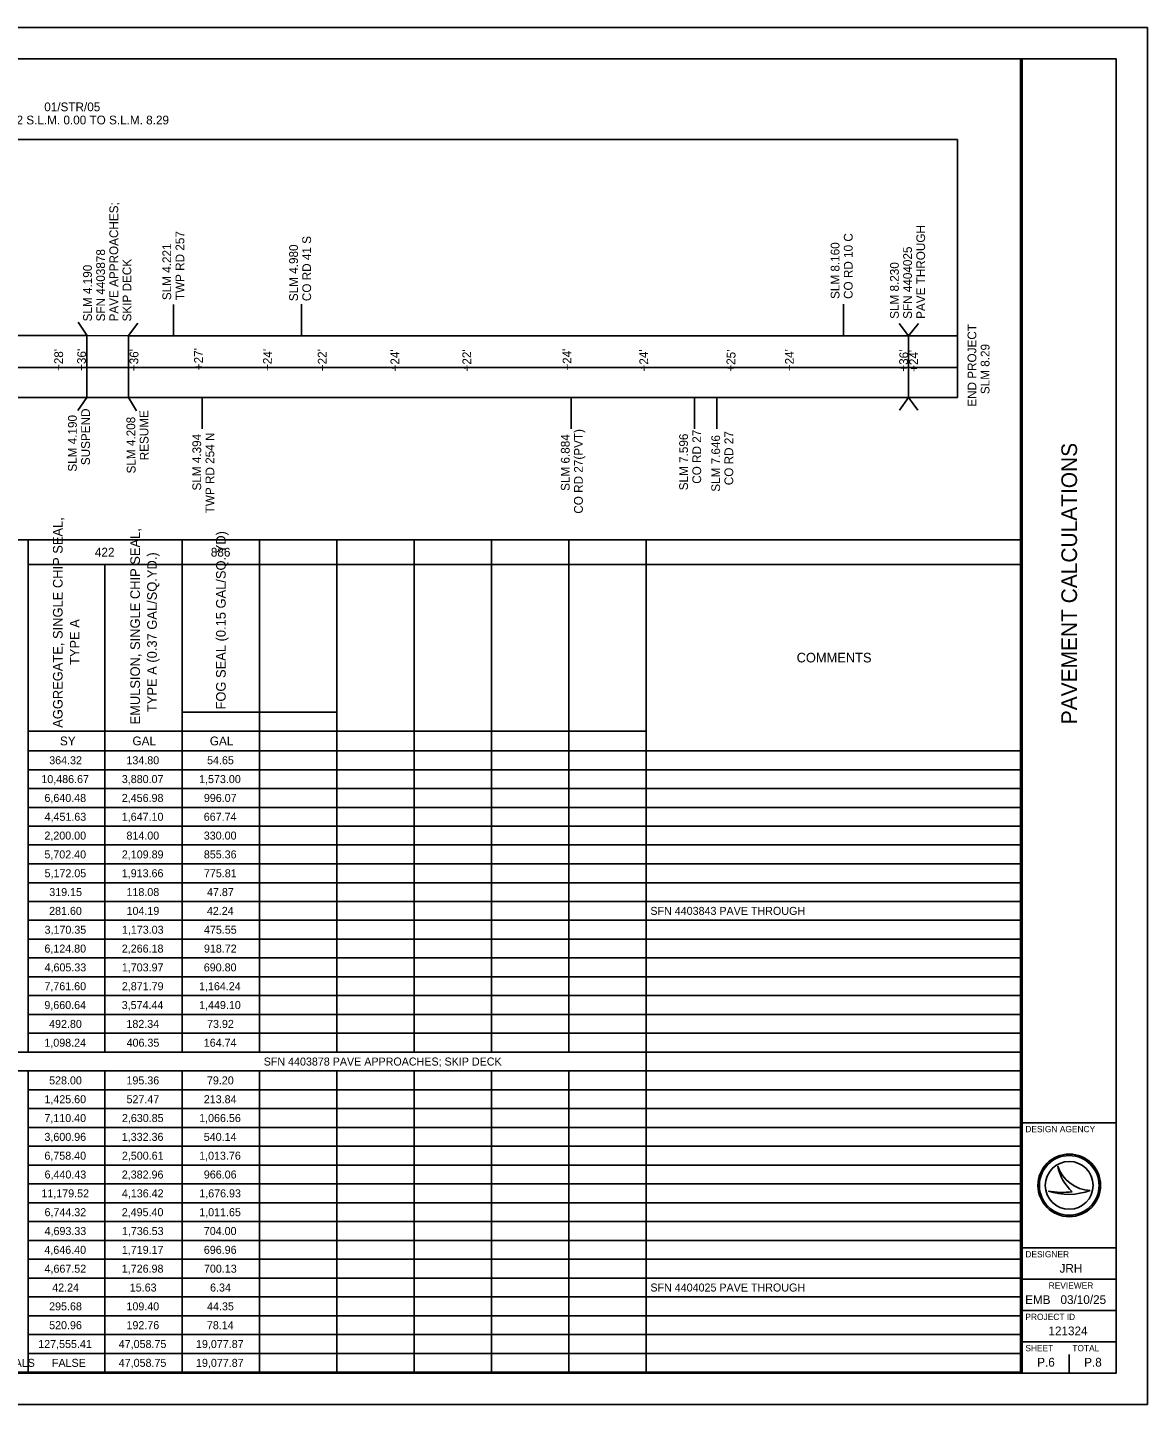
# Model space of a CAD drawing. Extents: x 0 to 680, y 0 to 440.
# Drawn here: x 322.2 to 680, y 0 to 440 of the extents above; entities that cross this region are included whole.
import ezdxf

# ---------------------------------------------------------------- set-up
doc = ezdxf.new("R2010")
doc.units = 0
for name, color, linetype in [('Default', 7, 'Continuous'), ('SH_Border', 7, 'Continuous'), ('SH_Cut_Line', 7, 'Continuous'), ('SH_Data', 7, 'Continuous'), ('SH_Text', 7, 'Continuous')]:
    doc.layers.add(name, color=color, linetype=linetype)

msp = doc.modelspace()

# ---------------------------------------------------------------- linework, layer by layer
at = {"layer": 'Default'}
for p, q in [((30, 430), (639.48, 430)), ((639.48, 430), (639.48, 10.29)), ((50.79, 404.2), (619.28, 404.2)), ((619.28, 381.75), (619.28, 404.2)), ((619.28, 404.2), (619.28, 341.75)), ((368.88, 341.52), (368.88, 351.52)), ((409.72, 341.56), (409.72, 351.56)), ((582.86, 341.61), (582.86, 351.61)), ((603.7, 341.5), (600.65, 345.46)), ((603.7, 341.5), (606.81, 345.41)), ((603.7, 321.77), (603.7, 341.49)), ((619.28, 341.75), (619.28, 321.78)), ((50.99, 331.41), (619.48, 331.36)), ((378.01, 321.75), (378.01, 311.75)), ((495.89, 321.8), (495.89, 311.8)), ((535.26, 321.78), (535.26, 311.78)), ((542.43, 321.77), (542.43, 311.77)), ((603.68, 321.78), (600.78, 317.71)), ((603.71, 321.78), (606.64, 317.73)), ((279.5, 276.26), (322.44, 276.26)), ((322, 276.26), (639.48, 276.26)), ((322.44, 276.26), (322.44, 112.59)), ((371.64, 276.26), (371.64, 112.59)), ((396.34, 276.26), (396.34, 112.59)), ((421.05, 276.26), (421.05, 112.59)), ((445.76, 276.26), (445.76, 112.59)), ((470.47, 276.26), (470.47, 112.59)), ((495.18, 276.26), (495.18, 112.59)), ((519.89, 276.26), (519.89, 10.29)), ((322.44, 268.44), (639.48, 268.44)), ((346.93, 268.44), (346.93, 112.59)), ((371.64, 221.2), (421.05, 221.2)), ((322.44, 215.18), (519.89, 215.18)), ((322.44, 208.86), (639.48, 208.86)), ((322.44, 202.85), (639.48, 202.85)), ((322.44, 196.83), (639.48, 196.83)), ((322.44, 190.81), (639.48, 190.81)), ((322.44, 184.79), (639.48, 184.79)), ((322.44, 178.78), (639.48, 178.78)), ((322.44, 172.76), (639.48, 172.76)), ((322.44, 166.74), (639.48, 166.74)), ((322.44, 160.73), (639.48, 160.73)), ((322.44, 154.71), (639.48, 154.71)), ((322.44, 148.69), (639.48, 148.69)), ((322.44, 142.67), (639.48, 142.67)), ((322.44, 136.66), (639.48, 136.66)), ((322.44, 130.64), (639.48, 130.64)), ((322.44, 124.62), (639.48, 124.62)), ((322.44, 118.6), (639.48, 118.6)), ((30, 112.59), (322.44, 112.59)), ((322, 112.59), (639.48, 112.59)), ((30, 106.57), (322.44, 106.57)), ((322, 106.57), (639.48, 106.57)), ((322.44, 106.57), (322.44, 10.29)), ((346.93, 106.57), (346.93, 10.29)), ((371.64, 106.57), (371.64, 10.29)), ((396.34, 106.57), (396.34, 10.29)), ((421.05, 106.57), (421.05, 10.29)), ((445.76, 106.57), (445.76, 10.29)), ((470.47, 106.57), (470.47, 10.29)), ((495.18, 106.57), (495.18, 10.29)), ((322.44, 100.55), (639.48, 100.55)), ((322.44, 94.53), (639.48, 94.53)), ((322.44, 88.52), (639.48, 88.52)), ((322.44, 82.5), (639.48, 82.5)), ((322.44, 76.48), (639.48, 76.48)), ((322.44, 70.47), (639.48, 70.47)), ((322.44, 64.45), (639.48, 64.45)), ((322.44, 58.43), (639.48, 58.43)), ((322.44, 52.41), (639.48, 52.41)), ((322.44, 46.4), (639.48, 46.4)), ((322.44, 40.38), (639.48, 40.38)), ((322.44, 34.36), (639.48, 34.36)), ((322.44, 28.34), (639.48, 28.34)), ((322.44, 22.33), (639.48, 22.33)), ((322.44, 16.31), (639.48, 16.31)), ((30, 10.29), (322.44, 10.29)), ((322, 10.29), (639.48, 10.29))]:
    msp.add_line(p, q, dxfattribs=at)
at = {"layer": 'SH_Border'}
for p, q in [((640, 10), (640, 430)), ((640, 90), (670, 90)), ((640, 50), (670, 50)), ((640, 40), (670, 40)), ((640, 30), (670, 30)), ((640, 20), (670, 20))]:
    msp.add_line(p, q, dxfattribs=at)
msp.add_lwpolyline([(30, 430), (670, 430), (670, 10), (30, 10)], close=True, dxfattribs=at)
at = {"layer": 'SH_Cut_Line'}
msp.add_lwpolyline([(0, 0), (680, 0), (680, 440), (0, 440)], close=True, dxfattribs=at)
at = {"layer": 'SH_Data'}
for p, q in [((651.35, 76.19), (651.35, 76.19)), ((648.34, 68.19), (648.34, 68.19)), ((655, 70), (655, 70)), ((661.75, 68.37), (661.75, 68.37)), ((647.5, 13.5), (647.5, 13.5)), ((655, 10), (655, 16))]:
    msp.add_line(p, q, dxfattribs=at)
for radius in [10, 9.54, 9.54, 7.64]:
    msp.add_circle((655, 70), radius, dxfattribs=at)
for centre, radius, start, end in [((662.32, 79.95), 11.6, 198.9257, 198.9319), ((666.93, 79.4), 15.91, 191.6379, 191.6421), ((662.32, 79.95), 11.6, 198.9319, 267.1657), ((666.93, 79.4), 15.91, 191.6421, 226.0947), ((654.79, 87.4), 20.26, 251.4576, 290.0832), ((652.96, 93.09), 25.32, 259.4964, 259.4995), ((654.79, 87.4), 20.26, 251.4527, 251.4576), ((652.96, 93.09), 25.32, 259.4995, 276.6672)]:
    msp.add_arc(centre, radius, start, end, dxfattribs=at)
at = {"layer": 'SH_Text'}
for p, q in [((341.13, 341.72), (338.36, 345.88)), ((354.43, 341.58), (357.47, 345.55)), ((50.76, 341.74), (619.36, 341.5)), ((341.18, 341.72), (341.18, 321.76)), ((354.47, 341.63), (354.47, 321.75)), ((50.99, 331.41), (619.48, 331.36)), ((50.79, 321.78), (619.28, 321.78)), ((341.15, 321.73), (338.33, 317.6)), ((354.47, 321.77), (357.02, 317.47))]:
    msp.add_line(p, q, dxfattribs=at)
for points in [[(341.18, 341.62), (341.18, 331.38), (199.88, 331.39), (341.18, 331.38), (341.18, 321.78), (50.79, 321.78), (50.79, 341.74)], [(619.28, 341.5), (619.28, 331.36), (354.48, 331.28), (354.48, 341.51)], [(619.28, 331.36), (619.28, 321.78), (341.18, 321.78), (341.18, 331.38)]]:
    msp.add_lwpolyline(points, close=True, dxfattribs=at)

# ---------------------------------------------------------------- texts
at = {"layer": 'Default'}
for s, height, p in [('01/STR/05', 2.8, (327.56, 413.25)), ('LAW-522 S.L.M. 0.00 TO S.L.M. 8.29', 2.8, (305.18, 409.05)), ('422', 2.813, (343.73, 270.94)), ('886', 2.813, (380.76, 270.94)), ('COMMENTS', 3.069, (567.92, 237.12)), ('SY', 2.813, (332.56, 210.62)), ('GAL', 2.813, (355.74, 210.62)), ('GAL', 2.813, (380.45, 210.62)), ('364.32', 2.557, (329.15, 204.58)), ('134.80', 2.557, (353.82, 204.58)), ('54.65', 2.557, (379.58, 204.58)), ('10,486.67', 2.557, (326.63, 198.56)), ('3,880.07', 2.557, (352.34, 198.56)), ('1,573.00', 2.557, (377.03, 198.56)), ('6,640.48', 2.557, (327.62, 192.54)), ('2,456.98', 2.557, (352.33, 192.54)), ('996.07', 2.557, (378.55, 192.54)), ('4,451.63', 2.557, (327.66, 186.52)), ('1,647.10', 2.557, (352.32, 186.52)), ('667.74', 2.557, (378.52, 186.52)), ('2,200.00', 2.557, (327.61, 180.51)), ('814.00', 2.557, (353.82, 180.51)), ('330.00', 2.557, (378.53, 180.51)), ('5,702.40', 2.557, (327.61, 174.49)), ('2,109.89', 2.557, (352.35, 174.49)), ('855.36', 2.557, (378.54, 174.49)), ('5,172.05', 2.557, (327.66, 168.47)), ('1,913.66', 2.557, (352.33, 168.47)), ('775.81', 2.557, (378.57, 168.47)), ('319.15', 2.557, (329.16, 162.46)), ('118.08', 2.557, (353.83, 162.46)), ('47.87', 2.557, (379.56, 162.46)), ('281.60', 2.557, (329.11, 156.44)), ('104.19', 2.557, (353.85, 156.44)), ('42.24', 2.557, (379.52, 156.44)), ('SFN 4403843 PAVE THROUGH', 2.5574, (521.2, 156.44)), ('3,170.35', 2.557, (327.66, 150.42)), ('1,173.03', 2.557, (352.37, 150.42)), ('475.55', 2.557, (378.58, 150.42)), ('6,124.80', 2.557, (327.61, 144.4)), ('2,266.18', 2.557, (352.33, 144.4)), ('918.72', 2.557, (378.57, 144.4)), ('4,605.33', 2.557, (327.66, 138.39)), ('1,703.97', 2.557, (352.34, 138.39)), ('690.80', 2.557, (378.53, 138.39)), ('7,761.60', 2.557, (327.61, 132.37)), ('2,871.79', 2.557, (352.35, 132.37)), ('1,164.24', 2.557, (377.01, 132.37)), ('9,660.64', 2.557, (327.6, 126.35)), ('3,574.44', 2.557, (352.31, 126.35)), ('1,449.10', 2.557, (377.03, 126.35)), ('492.80', 2.557, (329.11, 120.33)), ('182.34', 2.557, (353.81, 120.33)), ('73.92', 2.557, (379.58, 120.33)), ('1,098.24', 2.557, (327.6, 114.32)), ('406.35', 2.557, (353.87, 114.32)), ('164.74', 2.557, (378.52, 114.32)), ('SFN 4403878 PAVE APPROACHES; SKIP DECK', 2.5574, (397.66, 108.3)), ('528.00', 2.557, (329.11, 102.28)), ('195.36', 2.557, (353.83, 102.28)), ('79.20', 2.557, (379.53, 102.28)), ('1,425.60', 2.557, (327.61, 96.26)), ('527.47', 2.557, (353.84, 96.26)), ('213.84', 2.557, (378.52, 96.26)), ('7,110.40', 2.557, (327.61, 90.25)), ('2,630.85', 2.557, (352.37, 90.25)), ('1,066.56', 2.557, (377.04, 90.25)), ('3,600.96', 2.557, (327.62, 84.23)), ('1,332.36', 2.557, (352.33, 84.23)), ('540.14', 2.557, (378.52, 84.23)), ('6,758.40', 2.557, (327.61, 78.21)), ('2,500.61', 2.557, (352.36, 78.21)), ('1,013.76', 2.557, (377.04, 78.21)), ('6,440.43', 2.557, (327.66, 72.2)), ('2,382.96', 2.557, (352.33, 72.2)), ('966.06', 2.557, (378.54, 72.2)), ('11,179.52', 2.557, (326.65, 66.18)), ('4,136.42', 2.557, (352.36, 66.18)), ('1,676.93', 2.557, (377.08, 66.18)), ('6,744.32', 2.557, (327.65, 60.16)), ('2,495.40', 2.557, (352.32, 60.16)), ('1,011.65', 2.557, (377.07, 60.16)), ('4,693.33', 2.557, (327.66, 54.14)), ('1,736.53', 2.557, (352.37, 54.14)), ('704.00', 2.557, (378.53, 54.14)), ('4,646.40', 2.557, (327.61, 48.13)), ('1,719.17', 2.557, (352.34, 48.13)), ('696.96', 2.557, (378.54, 48.13)), ('4,667.52', 2.557, (327.65, 42.11)), ('1,726.98', 2.557, (352.33, 42.11)), ('700.13', 2.557, (378.58, 42.11)), ('42.24', 2.557, (330.11, 36.09)), ('15.63', 2.557, (354.88, 36.09)), ('6.34', 2.557, (380.53, 36.09)), ('SFN 4404025 PAVE THROUGH', 2.5574, (521.2, 36.09)), ('295.68', 2.557, (329.12, 30.07)), ('109.40', 2.557, (353.82, 30.07)), ('44.35', 2.557, (379.58, 30.07)), ('520.96', 2.557, (329.12, 24.06)), ('192.76', 2.557, (353.83, 24.06)), ('78.14', 2.557, (379.52, 24.06)), ('127,555.41', 2.557, (325.64, 18.04)), ('47,058.75', 2.557, (351.36, 18.04)), ('19,077.87', 2.557, (376.04, 18.04)), ('THIS SHEET TOTALS', 2.5574, (290.15, 12.02)), ('FALSE', 2.557, (330.01, 12.02)), ('47,058.75', 2.557, (351.36, 12.02)), ('19,077.87', 2.557, (376.04, 12.02))]:
    msp.add_text(s, height=height, dxfattribs=at).set_placement(p)
for s, height, rotation, p in [('PAVE APPROACHES;', 2.8, 90, (351.17, 346.09)), ('TWP RD 257', 2.8, 90, (372.3, 352.89)), ('CO RD 10 C', 2.8, 90, (585.81, 353.27)), ('PAVE THROUGH', 2.8, 90, (608.96, 346.91)), ('SLM 4.221', 2.8, 90, (368.1, 352.89)), ('SLM 4.980', 2.8, 90, (408.6, 352.57)), ('CO RD 41 S', 2.8, 90, (412.8, 352.57)), ('SLM 8.160', 2.8, 90, (581.61, 353.27)), ('SFN 4404025', 2.8, 90, (604.76, 346.91)), ('SFN 4403878', 2.8, 90, (346.97, 346.09)), ('SKIP DECK', 2.8, 90, (355.37, 346.09)), ('SLM 4.190', 2.8, 90, (342.77, 346.09)), ('SLM 8.230', 2.8, 90, (600.56, 346.91)), ('END PROJECT', 2.8, 90, (625.33, 318.82)), ("+28'", 2.8, 89.3296, (333.51, 330.21)), ("+36'", 2.8, 88.6689, (340.79, 330.23)), ("+36'", 2.8, 88.6689, (357.53, 330.17)), ("+27'", 2.8, 90.7703, (378.28, 330.52)), ("+24'", 2.8, 88.5554, (400.17, 330.19)), ("+22'", 2.8, 90.7703, (417.81, 330.19)), ("+24'", 2.8, 90.8026, (441.03, 330.11)), ("+22'", 2.8, 90.7703, (464, 330.11)), ("+24'", 2.8, 91.2033, (496.04, 330.37)), ("+24'", 2.8, 91.2033, (520.55, 330.13)), ("+25'", 2.8, 87.8363, (548.2, 329.97)), ("+24'", 2.8, 90.7703, (567.06, 330.18)), ("+36'", 2.8, 88.6689, (603.42, 329.98)), ("+24'", 2.8, 91.2033, (606.78, 329.98)), ('SLM 8.29', 2.8, 90, (629.53, 322.86)), ('       SLM 4.394', 2.8, 90, (377.68, 284.77)), ('TWP RD 254 N', 2.8, 90, (381.88, 284.77)), ('       SLM 6.884', 2.8, 90, (495.41, 284.65)), ('CO RD 27(PVT)', 2.8, 90, (499.61, 284.65)), ('SLM 7.596', 2.8, 90, (533.21, 292.13)), ('  CO RD 27', 2.8, 90, (537.41, 292.13)), ('SLM 7.646', 2.8, 90, (543.46, 291.67)), ('  CO RD 27', 2.8, 90, (547.66, 291.67)), ('AGGREGATE, SINGLE CHIP SEAL, ', 3.0803, 90, (333.42, 216.23)), ('EMULSION, SINGLE CHIP SEAL, ', 3.0803, 90, (358.13, 217.3)), ('FOG SEAL (0.15 GAL/SQ. YD)', 3.0803, 90, (385.53, 222.08)), ('TYPE A (0.37 GAL/SQ.YD.)', 3.0803, 90, (363.52, 221.25)), ('TYPE A', 3.08, 90, (338.81, 236.29))]:
    msp.add_text(s, height=height, rotation=rotation, dxfattribs=at).set_placement(p)
at = {"layer": 'SH_Data'}
msp.add_text('PAVEMENT CALCULATIONS', height=5, rotation=90, dxfattribs=at).set_placement((657.5, 217.37))
for s, height, p in [('DESIGN AGENCY', 2, (641, 87)), ('DESIGNER', 2, (641, 47)), ('JRH', 2.8, (651.91, 42.1)), ('REVIEWER', 2, (648.44, 37)), ('EMB', 2.8, (640.93, 32.1)), ('03/10/25', 2.8, (652.22, 32.1)), ('PROJECT ID', 2, (641, 27)), ('121324', 2.8, (648.36, 22.1)), ('SHEET', 2, (641, 17)), ('TOTAL', 2, (656, 17)), ('P.6', 2.8, (644.77, 12.1)), ('P.8', 2.8, (659.78, 12.1))]:
    msp.add_text(s, height=height, dxfattribs=at).set_placement(p)
at = {"layer": 'SH_Text'}
for s, rotation, p in [('  SUSPEND', 90, (342.15, 298.08)), ('    RESUME', 90.4525, (360.94, 297.56)), ('SLM 4.190', 90, (337.95, 298.08)), ('SLM 4.208', 90.4525, (356.74, 297.52))]:
    msp.add_text(s, height=2.8, rotation=rotation, dxfattribs=at).set_placement(p)

doc.saveas('drawing.dxf')
